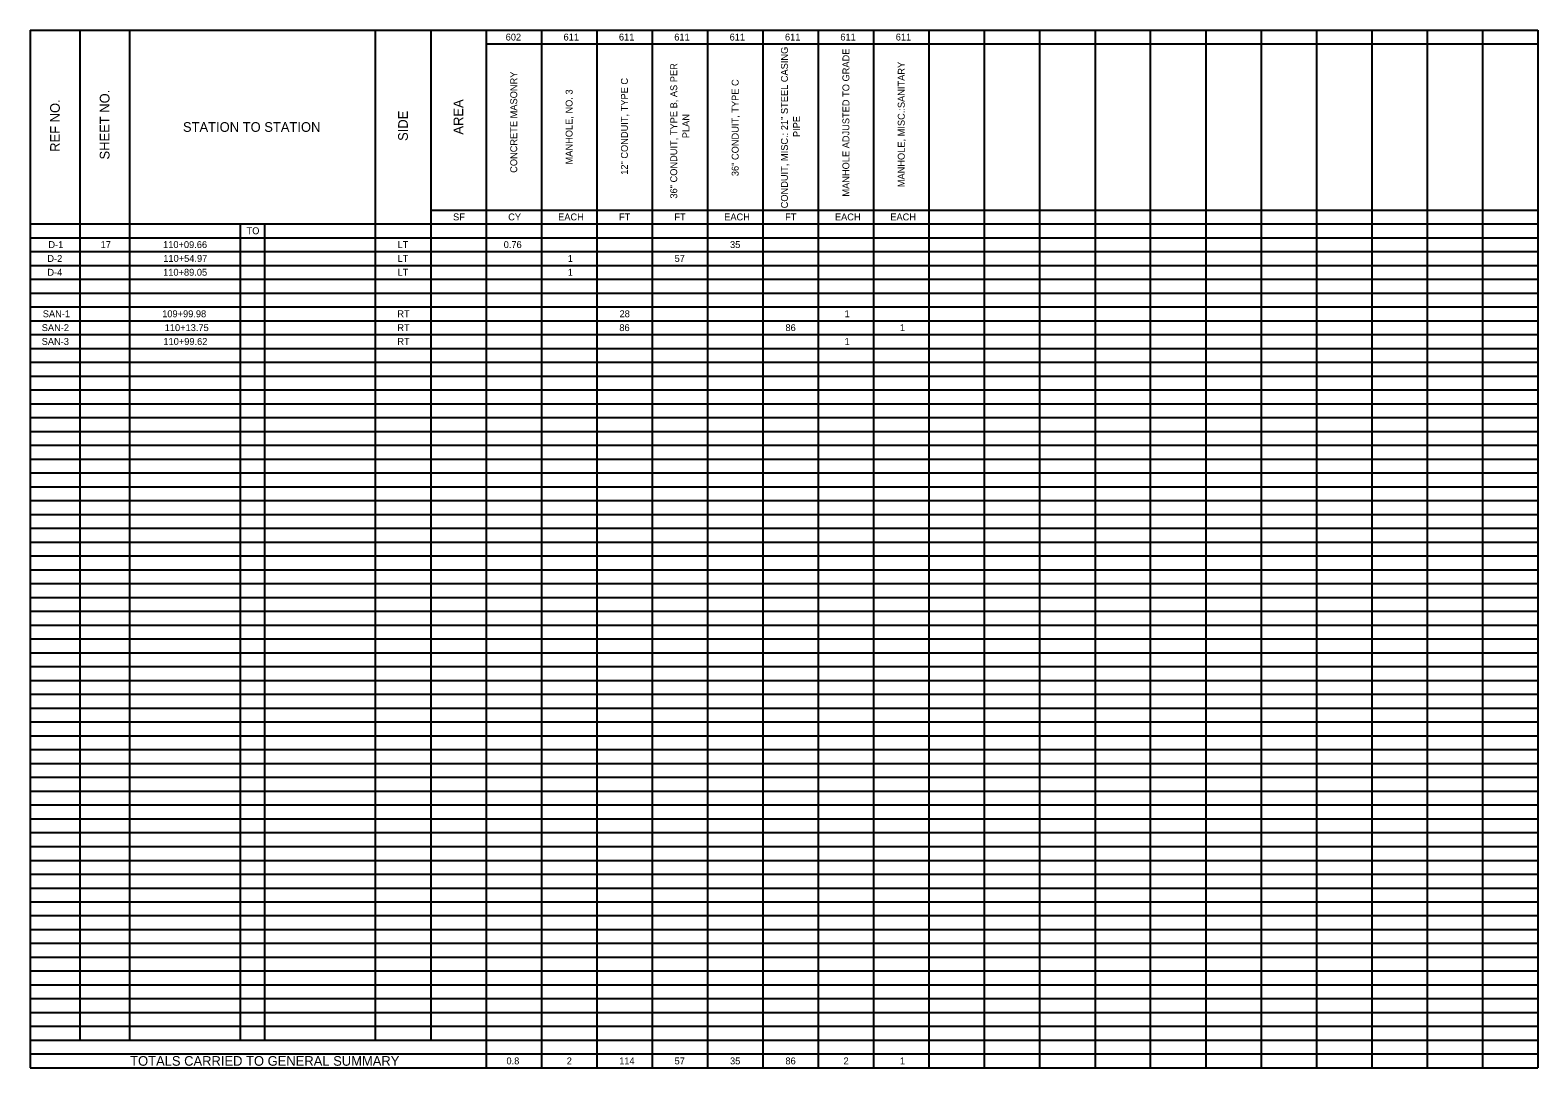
# Model space of a CAD drawing. Extents: x 0 to 76.2, y -27.8 to 22.
# Drawn here: x 45.7 to 76.2, y -27.78 to -6.78 of the extents above; entities that cross this region are included whole.
import ezdxf

# ---------------------------------------------------------------- set-up
doc = ezdxf.new("R2010")
doc.units = 0
doc.layers.add('Default', color=7, linetype='Continuous')

msp = doc.modelspace()

# ---------------------------------------------------------------- linework, layer by layer
at = {"layer": 'Default'}
for p, q in [((45.702, -6.782), (76.204, -6.782)), ((45.702, -6.782), (45.702, -27.781)), ((46.706, -6.782), (46.706, -27.221)), ((47.711, -6.782), (47.711, -27.221)), ((52.685, -6.782), (52.685, -27.221)), ((53.805, -6.782), (53.805, -27.221)), ((54.925, -6.782), (54.925, -27.781)), ((56.045, -6.782), (56.045, -27.781)), ((57.165, -6.782), (57.165, -27.781)), ((58.285, -6.782), (58.285, -27.781)), ((59.405, -6.782), (59.405, -27.781)), ((60.525, -6.782), (60.525, -27.781)), ((61.645, -6.782), (61.645, -27.781)), ((62.765, -6.782), (62.765, -27.781)), ((63.885, -6.782), (63.885, -27.781)), ((65.005, -6.782), (65.005, -27.781)), ((66.125, -6.782), (66.125, -27.781)), ((67.245, -6.782), (67.245, -27.781)), ((68.364, -6.782), (68.364, -27.781)), ((69.484, -6.782), (69.484, -27.781)), ((70.604, -6.782), (70.604, -27.781)), ((71.724, -6.782), (71.724, -27.781)), ((72.844, -6.782), (72.844, -27.781)), ((73.964, -6.782), (73.964, -27.781)), ((75.084, -6.782), (75.084, -27.781)), ((76.204, -6.782), (76.204, -27.781)), ((54.925, -7.062), (76.204, -7.062)), ((53.805, -10.422), (76.204, -10.422)), ((45.702, -10.702), (76.204, -10.702)), ((49.951, -10.702), (49.951, -27.221)), ((50.445, -10.702), (50.445, -27.221)), ((45.702, -10.982), (76.204, -10.982)), ((45.702, -11.262), (76.204, -11.262)), ((45.702, -11.542), (76.204, -11.542)), ((45.702, -11.822), (76.204, -11.822)), ((45.702, -12.102), (76.204, -12.102)), ((45.702, -12.382), (76.204, -12.382)), ((45.702, -12.662), (76.204, -12.662)), ((45.702, -12.942), (76.204, -12.942)), ((45.702, -13.222), (76.204, -13.222)), ((45.702, -13.502), (76.204, -13.502)), ((45.702, -13.782), (76.204, -13.782)), ((45.702, -14.062), (76.204, -14.062)), ((45.702, -14.342), (76.204, -14.342)), ((45.702, -14.622), (76.204, -14.622)), ((45.702, -14.902), (76.204, -14.902)), ((45.702, -15.182), (76.204, -15.182)), ((45.702, -15.462), (76.204, -15.462)), ((45.702, -15.742), (76.204, -15.742)), ((45.702, -16.022), (76.204, -16.022)), ((45.702, -16.302), (76.204, -16.302)), ((45.702, -16.582), (76.204, -16.582)), ((45.702, -16.862), (76.204, -16.862)), ((45.702, -17.142), (76.204, -17.142)), ((45.702, -17.422), (76.204, -17.422)), ((45.702, -17.702), (76.204, -17.702)), ((45.702, -17.982), (76.204, -17.982)), ((45.702, -18.262), (76.204, -18.262)), ((45.702, -18.542), (76.204, -18.542)), ((45.702, -18.822), (76.204, -18.822)), ((45.702, -19.102), (76.204, -19.102)), ((45.702, -19.382), (76.204, -19.382)), ((45.702, -19.662), (76.204, -19.662)), ((45.702, -19.942), (76.204, -19.942)), ((45.702, -20.222), (76.204, -20.222)), ((45.702, -20.502), (76.204, -20.502)), ((45.702, -20.782), (76.204, -20.782)), ((45.702, -21.062), (76.204, -21.062)), ((45.702, -21.342), (76.204, -21.342)), ((45.702, -21.622), (76.204, -21.622)), ((45.702, -21.902), (76.204, -21.902)), ((45.702, -22.182), (76.204, -22.182)), ((45.702, -22.462), (76.204, -22.462)), ((45.702, -22.742), (76.204, -22.742)), ((45.702, -23.022), (76.204, -23.022)), ((45.702, -23.302), (76.204, -23.302)), ((45.702, -23.582), (76.204, -23.582)), ((45.702, -23.862), (76.204, -23.862)), ((45.702, -24.142), (76.204, -24.142)), ((45.702, -24.421), (76.204, -24.421)), ((45.702, -24.701), (76.204, -24.701)), ((45.702, -24.981), (76.204, -24.981)), ((45.702, -25.261), (76.204, -25.261)), ((45.702, -25.541), (76.204, -25.541)), ((45.702, -25.821), (76.204, -25.821)), ((45.702, -26.101), (76.204, -26.101)), ((45.702, -26.381), (76.204, -26.381)), ((45.702, -26.661), (76.204, -26.661)), ((45.702, -26.941), (76.204, -26.941)), ((45.702, -27.221), (76.204, -27.221)), ((45.702, -27.501), (54.925, -27.501)), ((54.925, -27.501), (76.204, -27.501)), ((45.702, -27.781), (76.204, -27.781))]:
    msp.add_line(p, q, dxfattribs=at)

# ---------------------------------------------------------------- texts
for s, height, p in [('602', 0.14, (55.322, -6.992)), ('611', 0.14, (56.493, -6.992)), ('611', 0.14, (57.613, -6.992)), ('611', 0.14, (58.733, -6.992)), ('611', 0.14, (59.853, -6.992)), ('611', 0.14, (60.973, -6.992)), ('611', 0.14, (62.093, -6.992)), ('611', 0.14, (63.213, -6.992)), ('STATION TO STATION', 0.196, (48.793, -8.84)), ('SF', 0.14, (54.258, -10.632)), ('CY', 0.14, (55.373, -10.632)), ('EACH', 0.14, (56.383, -10.632)), ('FT', 0.14, (57.615, -10.632)), ('FT', 0.14, (58.735, -10.632)), ('EACH', 0.14, (59.743, -10.632)), ('FT', 0.14, (60.975, -10.632)), ('EACH', 0.14, (61.983, -10.632)), ('EACH', 0.14, (63.103, -10.632)), ('TO', 0.14, (50.08, -10.912)), ('D-1', 0.14, (46.071, -11.192)), ('17', 0.14, (47.128, -11.192)), ('110+09.66', 0.14, (48.391, -11.192)), ('LT', 0.14, (53.135, -11.192)), ('0.76', 0.14, (55.282, -11.192)), ('35', 0.14, (59.861, -11.192)), ('D-2', 0.14, (46.05, -11.472)), ('110+54.97', 0.14, (48.395, -11.472)), ('LT', 0.14, (53.135, -11.472)), ('1', 0.14, (56.579, -11.472)), ('57', 0.14, (58.739, -11.472)), ('D-4', 0.14, (46.05, -11.752)), ('110+89.05', 0.14, (48.392, -11.752)), ('LT', 0.14, (53.135, -11.752)), ('1', 0.14, (56.579, -11.752)), ('SAN-1', 0.14, (45.957, -12.592)), ('109+99.98', 0.14, (48.373, -12.592)), ('RT', 0.14, (53.131, -12.592)), ('28', 0.14, (57.626, -12.592)), ('1', 0.14, (62.178, -12.592)), ('SAN-2', 0.14, (45.936, -12.872)), ('110+13.75', 0.14, (48.424, -12.872)), ('RT', 0.14, (53.131, -12.872)), ('86', 0.14, (57.622, -12.872)), ('86', 0.14, (60.982, -12.872)), ('1', 0.14, (63.298, -12.872)), ('SAN-3', 0.14, (45.935, -13.152)), ('110+99.62', 0.14, (48.397, -13.152)), ('RT', 0.14, (53.131, -13.152)), ('1', 0.14, (62.178, -13.152)), ('TOTALS CARRIED TO GENERAL SUMMARY', 0.196, (47.725, -27.739)), ('0.8', 0.14, (55.338, -27.711)), ('2', 0.14, (56.558, -27.711)), ('114', 0.14, (57.619, -27.711)), ('57', 0.14, (58.739, -27.711)), ('35', 0.14, (59.861, -27.711)), ('86', 0.14, (60.982, -27.711)), ('2', 0.14, (62.158, -27.711)), ('1', 0.14, (63.298, -27.711))]:
    msp.add_text(s, height=height, dxfattribs=at).set_placement(p)
for s, height, p in [('CONDUIT, MISC.: 21" STEEL CASING ', 0.14, (61.032, -10.388)), ('MANHOLE ADJUSTED TO GRADE', 0.14, (62.275, -10.151)), ('CONCRETE MASONRY', 0.14, (55.555, -9.67)), ('36" CONDUIT, TYPE B, AS PER ', 0.14, (58.792, -10.191)), ('MANHOLE, MISC.:SANITARY', 0.14, (63.395, -9.961)), ('12" CONDUIT, TYPE C', 0.14, (57.795, -9.709)), ('36" CONDUIT, TYPE C', 0.14, (60.035, -9.737)), ('REF NO.', 0.196, (46.302, -9.245)), ('SHEET NO.', 0.196, (47.307, -9.4)), ('AREA', 0.196, (54.463, -8.896)), ('MANHOLE, NO. 3', 0.14, (56.675, -9.5)), ('SIDE', 0.196, (53.343, -9.023)), ('PLAN', 0.14, (59.037, -8.968)), ('PIPE', 0.14, (61.277, -8.946))]:
    msp.add_text(s, height=height, rotation=90, dxfattribs=at).set_placement(p)

doc.saveas('drawing.dxf')
